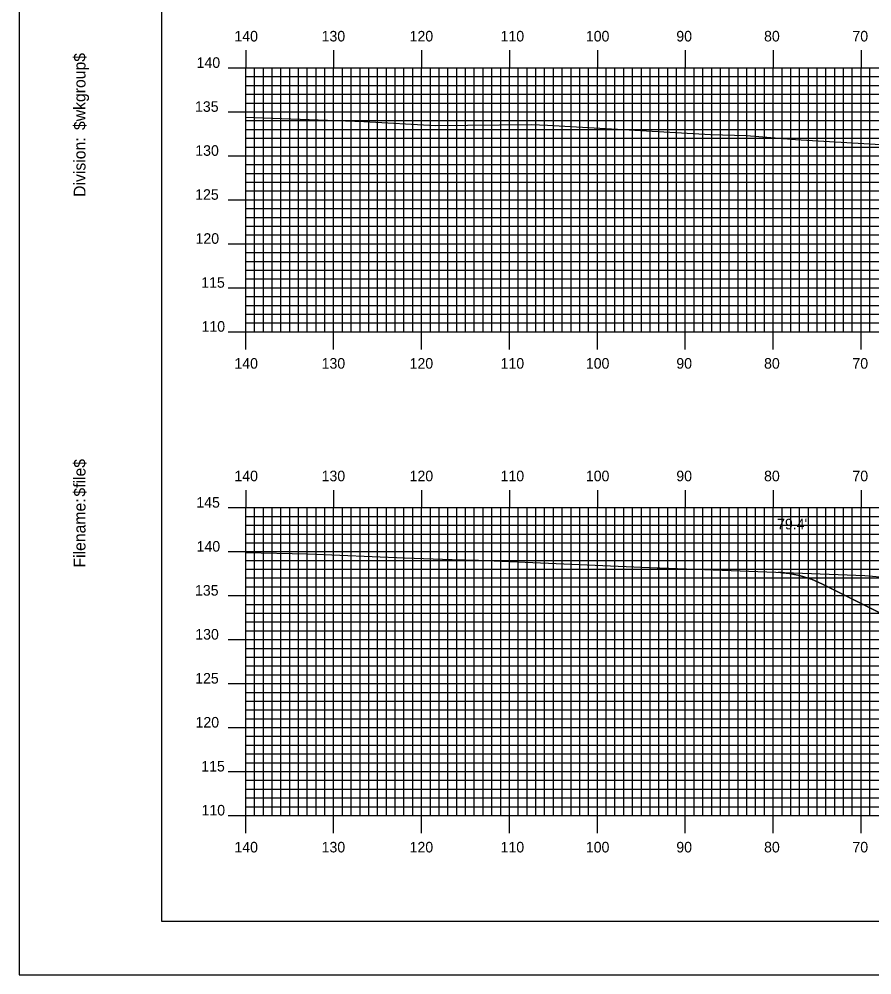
# Model space of a CAD drawing. Extents: x 1770842 to 1771185, y 442591 to 442811.
# Drawn here: x 1770841.8 to 1770938.8, y 442590.5 to 442699.2 of the extents above; entities that cross this region are included whole.
import ezdxf

# ---------------------------------------------------------------- set-up
doc = ezdxf.new("R2010")
doc.units = 0
for name, color, linetype in [('BORDER', 7, 'Continuous'), ('D_Roadway_Centerline', 7, 'Continuous'), ('D_Roadway_SlopeLines', 7, 'Continuous'), ('D_Text_Standard', 7, 'Continuous'), ('H_V ANNOTATION', 7, 'Continuous'), ('MAJOR', 7, 'Continuous'), ('MINOR', 7, 'Continuous'), ('PLOT BOUNDARY', 7, 'Continuous'), ('S_Roadway_Centerline', 7, 'Continuous')]:
    doc.layers.add(name, color=color, linetype=linetype)

msp = doc.modelspace()

# ---------------------------------------------------------------- linework, layer by layer
at = {"layer": 'BORDER'}
msp.add_lwpolyline([(1770857.95, 442596.67), (1771177.95, 442596.67), (1771177.95, 442806.67), (1770857.95, 442806.67)], close=True, dxfattribs=at)
at = {"layer": 'D_Roadway_Centerline'}
msp.add_lwpolyline([(1770928.14, 442636.32), (1770928.6, 442636.27), (1770929.39, 442636.2), (1770930.36, 442635.99), (1770930.64, 442635.93), (1770931.48, 442635.66), (1770931.89, 442635.53), (1770933.14, 442634.97), (1770933.14, 442634.97), (1770955.81, 442623.64), (1770973.37, 442614.86), (1770973.38, 442614.85), (1770977.38, 442615.85), (1770977.38, 442615.85), (1770987.55, 442618.4), (1770995.55, 442618.72), (1771007.55, 442618.96), (1771019.55, 442618.72), (1771027.55, 442618.4), (1771027.55, 442618.4), (1771037.73, 442615.85), (1771041.73, 442614.85), (1771041.74, 442614.86), (1771068.97, 442628.47)], dxfattribs=at)
at = {"layer": 'D_Roadway_SlopeLines'}
msp.add_lwpolyline([(1770973.38, 442614.85), (1770933.14, 442634.97), (1770931.89, 442635.53), (1770930.64, 442635.93), (1770929.39, 442636.2), (1770928.14, 442636.32)], dxfattribs=at)
at = {"layer": 'MAJOR'}
for p, q in [((1770867.55, 442695.67), (1770867.55, 442693.67)), ((1770877.55, 442695.67), (1770877.55, 442693.67)), ((1770887.55, 442695.67), (1770887.55, 442693.67)), ((1770897.55, 442695.67), (1770897.55, 442693.67)), ((1770907.55, 442695.67), (1770907.55, 442693.67)), ((1770917.55, 442695.67), (1770917.55, 442693.67)), ((1770927.55, 442695.67), (1770927.55, 442693.67)), ((1770937.55, 442695.67), (1770937.55, 442693.67)), ((1770865.55, 442693.67), (1770867.55, 442693.67)), ((1770867.55, 442693.67), (1771147.55, 442693.67)), ((1770867.55, 442663.67), (1770867.55, 442693.67)), ((1770867.55, 442663.67), (1770867.55, 442693.67)), ((1770867.55, 442693.67), (1771147.55, 442693.67)), ((1770877.55, 442663.67), (1770877.55, 442693.67)), ((1770887.55, 442663.67), (1770887.55, 442693.67)), ((1770897.55, 442663.67), (1770897.55, 442693.67)), ((1770907.55, 442663.67), (1770907.55, 442693.67)), ((1770917.55, 442663.67), (1770917.55, 442693.67)), ((1770927.55, 442663.67), (1770927.55, 442693.67)), ((1770937.55, 442663.67), (1770937.55, 442693.67)), ((1770865.55, 442688.67), (1770867.55, 442688.67)), ((1770867.55, 442688.67), (1771147.55, 442688.67)), ((1770865.55, 442683.67), (1770867.55, 442683.67)), ((1770867.55, 442683.67), (1771147.55, 442683.67)), ((1770865.55, 442678.67), (1770867.55, 442678.67)), ((1770867.55, 442678.67), (1771147.55, 442678.67)), ((1770865.55, 442673.67), (1770867.55, 442673.67)), ((1770867.55, 442673.67), (1771147.55, 442673.67)), ((1770865.55, 442668.67), (1770867.55, 442668.67)), ((1770867.55, 442668.67), (1771147.55, 442668.67)), ((1770865.55, 442663.67), (1770867.55, 442663.67)), ((1770867.55, 442663.67), (1771147.55, 442663.67)), ((1770867.55, 442663.67), (1771147.55, 442663.67)), ((1770867.55, 442661.66), (1770867.55, 442663.67)), ((1770877.55, 442661.66), (1770877.55, 442663.67)), ((1770887.55, 442661.66), (1770887.55, 442663.67)), ((1770897.55, 442661.66), (1770897.55, 442663.67)), ((1770907.55, 442661.66), (1770907.55, 442663.67)), ((1770917.55, 442661.66), (1770917.55, 442663.67)), ((1770927.55, 442661.66), (1770927.55, 442663.67)), ((1770937.55, 442661.66), (1770937.55, 442663.67)), ((1770867.55, 442645.67), (1770867.55, 442643.67)), ((1770877.55, 442645.67), (1770877.55, 442643.67)), ((1770887.55, 442645.67), (1770887.55, 442643.67)), ((1770897.55, 442645.67), (1770897.55, 442643.67)), ((1770907.55, 442645.67), (1770907.55, 442643.67)), ((1770917.55, 442645.67), (1770917.55, 442643.67)), ((1770927.55, 442645.67), (1770927.55, 442643.67)), ((1770937.55, 442645.67), (1770937.55, 442643.67)), ((1770865.55, 442643.67), (1770867.55, 442643.67)), ((1770867.55, 442643.67), (1771147.55, 442643.67)), ((1770867.55, 442608.67), (1770867.55, 442643.67)), ((1770867.55, 442608.67), (1770867.55, 442643.67)), ((1770867.55, 442643.67), (1771147.55, 442643.67)), ((1770877.55, 442608.67), (1770877.55, 442643.67)), ((1770887.55, 442608.67), (1770887.55, 442643.67)), ((1770897.55, 442608.67), (1770897.55, 442643.67)), ((1770907.55, 442608.67), (1770907.55, 442643.67)), ((1770917.55, 442608.67), (1770917.55, 442643.67)), ((1770927.55, 442608.67), (1770927.55, 442643.67)), ((1770937.55, 442608.67), (1770937.55, 442643.67)), ((1770865.55, 442638.67), (1770867.55, 442638.67)), ((1770867.55, 442638.67), (1771147.55, 442638.67)), ((1770865.55, 442633.67), (1770867.55, 442633.67)), ((1770867.55, 442633.67), (1771147.55, 442633.67)), ((1770865.55, 442628.67), (1770867.55, 442628.67)), ((1770867.55, 442628.67), (1771147.55, 442628.67)), ((1770865.55, 442623.67), (1770867.55, 442623.67)), ((1770867.55, 442623.67), (1771147.55, 442623.67)), ((1770865.55, 442618.67), (1770867.55, 442618.67)), ((1770867.55, 442618.67), (1771147.55, 442618.67)), ((1770865.55, 442613.67), (1770867.55, 442613.67)), ((1770867.55, 442613.67), (1771147.55, 442613.67)), ((1770865.55, 442608.67), (1770867.55, 442608.67)), ((1770867.55, 442608.67), (1771147.55, 442608.67)), ((1770867.55, 442608.67), (1771147.55, 442608.67)), ((1770867.55, 442606.66), (1770867.55, 442608.67)), ((1770877.55, 442606.66), (1770877.55, 442608.67)), ((1770887.55, 442606.66), (1770887.55, 442608.67)), ((1770897.55, 442606.66), (1770897.55, 442608.67)), ((1770907.55, 442606.66), (1770907.55, 442608.67)), ((1770917.55, 442606.66), (1770917.55, 442608.67)), ((1770927.55, 442606.66), (1770927.55, 442608.67)), ((1770937.55, 442606.66), (1770937.55, 442608.67))]:
    msp.add_line(p, q, dxfattribs=at)
at = {"layer": 'MINOR'}
for p, q in [((1770868.55, 442663.67), (1770868.55, 442693.67)), ((1770869.55, 442663.67), (1770869.55, 442693.67)), ((1770870.55, 442663.67), (1770870.55, 442693.67)), ((1770871.55, 442663.67), (1770871.55, 442693.67)), ((1770872.55, 442663.67), (1770872.55, 442693.67)), ((1770873.55, 442663.67), (1770873.55, 442693.67)), ((1770874.55, 442663.67), (1770874.55, 442693.67)), ((1770875.55, 442663.67), (1770875.55, 442693.67)), ((1770876.55, 442663.67), (1770876.55, 442693.67)), ((1770878.55, 442663.67), (1770878.55, 442693.67)), ((1770879.55, 442663.67), (1770879.55, 442693.67)), ((1770880.55, 442663.67), (1770880.55, 442693.67)), ((1770881.55, 442663.67), (1770881.55, 442693.67)), ((1770882.55, 442663.67), (1770882.55, 442693.67)), ((1770883.55, 442663.67), (1770883.55, 442693.67)), ((1770884.55, 442663.67), (1770884.55, 442693.67)), ((1770885.55, 442663.67), (1770885.55, 442693.67)), ((1770886.55, 442663.67), (1770886.55, 442693.67)), ((1770888.55, 442663.67), (1770888.55, 442693.67)), ((1770889.55, 442663.67), (1770889.55, 442693.67)), ((1770890.55, 442663.67), (1770890.55, 442693.67)), ((1770891.55, 442663.67), (1770891.55, 442693.67)), ((1770892.55, 442663.67), (1770892.55, 442693.67)), ((1770893.55, 442663.67), (1770893.55, 442693.67)), ((1770894.55, 442663.67), (1770894.55, 442693.67)), ((1770895.55, 442663.67), (1770895.55, 442693.67)), ((1770896.55, 442663.67), (1770896.55, 442693.67)), ((1770898.55, 442663.67), (1770898.55, 442693.67)), ((1770899.55, 442663.67), (1770899.55, 442693.67)), ((1770900.55, 442663.67), (1770900.55, 442693.67)), ((1770901.55, 442663.67), (1770901.55, 442693.67)), ((1770902.55, 442663.67), (1770902.55, 442693.67)), ((1770903.55, 442663.67), (1770903.55, 442693.67)), ((1770904.55, 442663.67), (1770904.55, 442693.67)), ((1770905.55, 442663.67), (1770905.55, 442693.67)), ((1770906.55, 442663.67), (1770906.55, 442693.67)), ((1770908.55, 442663.67), (1770908.55, 442693.67)), ((1770909.55, 442663.67), (1770909.55, 442693.67)), ((1770910.55, 442663.67), (1770910.55, 442693.67)), ((1770911.55, 442663.67), (1770911.55, 442693.67)), ((1770912.55, 442663.67), (1770912.55, 442693.67)), ((1770913.55, 442663.67), (1770913.55, 442693.67)), ((1770914.55, 442663.67), (1770914.55, 442693.67)), ((1770915.55, 442663.67), (1770915.55, 442693.67)), ((1770916.55, 442663.67), (1770916.55, 442693.67)), ((1770918.55, 442663.67), (1770918.55, 442693.67)), ((1770919.55, 442663.67), (1770919.55, 442693.67)), ((1770920.55, 442663.67), (1770920.55, 442693.67)), ((1770921.55, 442663.67), (1770921.55, 442693.67)), ((1770922.55, 442663.67), (1770922.55, 442693.67)), ((1770923.55, 442663.67), (1770923.55, 442693.67)), ((1770924.55, 442663.67), (1770924.55, 442693.67)), ((1770925.55, 442663.67), (1770925.55, 442693.67)), ((1770926.55, 442663.67), (1770926.55, 442693.67)), ((1770928.55, 442663.67), (1770928.55, 442693.67)), ((1770929.55, 442663.67), (1770929.55, 442693.67)), ((1770930.55, 442663.67), (1770930.55, 442693.67)), ((1770931.55, 442663.67), (1770931.55, 442693.67)), ((1770932.55, 442663.67), (1770932.55, 442693.67)), ((1770933.55, 442663.67), (1770933.55, 442693.67)), ((1770934.55, 442663.67), (1770934.55, 442693.67)), ((1770935.55, 442663.67), (1770935.55, 442693.67)), ((1770936.55, 442663.67), (1770936.55, 442693.67)), ((1770938.55, 442663.67), (1770938.55, 442693.67)), ((1770867.55, 442692.67), (1771147.55, 442692.67)), ((1770867.55, 442692.67), (1770869.56, 442692.67)), ((1770867.55, 442691.67), (1771147.55, 442691.67)), ((1770867.55, 442691.67), (1770869.56, 442691.67)), ((1770867.55, 442690.67), (1771147.55, 442690.67)), ((1770867.55, 442690.67), (1770869.56, 442690.67)), ((1770867.55, 442689.67), (1771147.55, 442689.67)), ((1770867.55, 442689.67), (1770869.56, 442689.67)), ((1770867.55, 442687.67), (1771147.55, 442687.67)), ((1770867.55, 442687.67), (1770869.56, 442687.67)), ((1770867.55, 442686.67), (1771147.55, 442686.67)), ((1770867.55, 442686.67), (1770869.56, 442686.67)), ((1770867.55, 442685.67), (1771147.55, 442685.67)), ((1770867.55, 442685.67), (1770869.56, 442685.67)), ((1770867.55, 442684.67), (1771147.55, 442684.67)), ((1770867.55, 442684.67), (1770869.56, 442684.67)), ((1770867.55, 442682.67), (1771147.55, 442682.67)), ((1770867.55, 442682.67), (1770869.56, 442682.67)), ((1770867.55, 442681.67), (1771147.55, 442681.67)), ((1770867.55, 442681.67), (1770869.56, 442681.67)), ((1770867.55, 442680.67), (1771147.55, 442680.67)), ((1770867.55, 442680.67), (1770869.56, 442680.67)), ((1770867.55, 442679.67), (1771147.55, 442679.67)), ((1770867.55, 442679.67), (1770869.56, 442679.67)), ((1770867.55, 442677.67), (1771147.55, 442677.67)), ((1770867.55, 442677.67), (1770869.56, 442677.67)), ((1770867.55, 442676.67), (1771147.55, 442676.67)), ((1770867.55, 442676.67), (1770869.56, 442676.67)), ((1770867.55, 442675.67), (1771147.55, 442675.67)), ((1770867.55, 442675.67), (1770869.56, 442675.67)), ((1770867.55, 442674.67), (1771147.55, 442674.67)), ((1770867.55, 442674.67), (1770869.56, 442674.67)), ((1770867.55, 442672.67), (1771147.55, 442672.67)), ((1770867.55, 442672.67), (1770869.56, 442672.67)), ((1770867.55, 442671.67), (1771147.55, 442671.67)), ((1770867.55, 442671.67), (1770869.56, 442671.67)), ((1770867.55, 442670.67), (1771147.55, 442670.67)), ((1770867.55, 442670.67), (1770869.56, 442670.67)), ((1770867.55, 442669.67), (1771147.55, 442669.67)), ((1770867.55, 442669.67), (1770869.56, 442669.67)), ((1770867.55, 442667.67), (1771147.55, 442667.67)), ((1770867.55, 442667.67), (1770869.56, 442667.67)), ((1770867.55, 442666.67), (1771147.55, 442666.67)), ((1770867.55, 442666.67), (1770869.56, 442666.67)), ((1770867.55, 442665.67), (1771147.55, 442665.67)), ((1770867.55, 442665.67), (1770869.56, 442665.67)), ((1770867.55, 442664.67), (1771147.55, 442664.67)), ((1770867.55, 442664.67), (1770869.56, 442664.67)), ((1770868.55, 442608.67), (1770868.55, 442643.67)), ((1770869.55, 442608.67), (1770869.55, 442643.67)), ((1770870.55, 442608.67), (1770870.55, 442643.67)), ((1770871.55, 442608.67), (1770871.55, 442643.67)), ((1770872.55, 442608.67), (1770872.55, 442643.67)), ((1770873.55, 442608.67), (1770873.55, 442643.67)), ((1770874.55, 442608.67), (1770874.55, 442643.67)), ((1770875.55, 442608.67), (1770875.55, 442643.67)), ((1770876.55, 442608.67), (1770876.55, 442643.67)), ((1770878.55, 442608.67), (1770878.55, 442643.67)), ((1770879.55, 442608.67), (1770879.55, 442643.67)), ((1770880.55, 442608.67), (1770880.55, 442643.67)), ((1770881.55, 442608.67), (1770881.55, 442643.67)), ((1770882.55, 442608.67), (1770882.55, 442643.67)), ((1770883.55, 442608.67), (1770883.55, 442643.67)), ((1770884.55, 442608.67), (1770884.55, 442643.67)), ((1770885.55, 442608.67), (1770885.55, 442643.67)), ((1770886.55, 442608.67), (1770886.55, 442643.67)), ((1770888.55, 442608.67), (1770888.55, 442643.67)), ((1770889.55, 442608.67), (1770889.55, 442643.67)), ((1770890.55, 442608.67), (1770890.55, 442643.67)), ((1770891.55, 442608.67), (1770891.55, 442643.67)), ((1770892.55, 442608.67), (1770892.55, 442643.67)), ((1770893.55, 442608.67), (1770893.55, 442643.67)), ((1770894.55, 442608.67), (1770894.55, 442643.67)), ((1770895.55, 442608.67), (1770895.55, 442643.67)), ((1770896.55, 442608.67), (1770896.55, 442643.67)), ((1770898.55, 442608.67), (1770898.55, 442643.67)), ((1770899.55, 442608.67), (1770899.55, 442643.67)), ((1770900.55, 442608.67), (1770900.55, 442643.67)), ((1770901.55, 442608.67), (1770901.55, 442643.67)), ((1770902.55, 442608.67), (1770902.55, 442643.67)), ((1770903.55, 442608.67), (1770903.55, 442643.67)), ((1770904.55, 442608.67), (1770904.55, 442643.67)), ((1770905.55, 442608.67), (1770905.55, 442643.67)), ((1770906.55, 442608.67), (1770906.55, 442643.67)), ((1770908.55, 442608.67), (1770908.55, 442643.67)), ((1770909.55, 442608.67), (1770909.55, 442643.67)), ((1770910.55, 442608.67), (1770910.55, 442643.67)), ((1770911.55, 442608.67), (1770911.55, 442643.67)), ((1770912.55, 442608.67), (1770912.55, 442643.67)), ((1770913.55, 442608.67), (1770913.55, 442643.67)), ((1770914.55, 442608.67), (1770914.55, 442643.67)), ((1770915.55, 442608.67), (1770915.55, 442643.67)), ((1770916.55, 442608.67), (1770916.55, 442643.67)), ((1770918.55, 442608.67), (1770918.55, 442643.67)), ((1770919.55, 442608.67), (1770919.55, 442643.67)), ((1770920.55, 442608.67), (1770920.55, 442643.67)), ((1770921.55, 442608.67), (1770921.55, 442643.67)), ((1770922.55, 442608.67), (1770922.55, 442643.67)), ((1770923.55, 442608.67), (1770923.55, 442643.67)), ((1770924.55, 442608.67), (1770924.55, 442643.67)), ((1770925.55, 442608.67), (1770925.55, 442643.67)), ((1770926.55, 442608.67), (1770926.55, 442643.67)), ((1770928.55, 442608.67), (1770928.55, 442643.67)), ((1770929.55, 442608.67), (1770929.55, 442643.67)), ((1770930.55, 442608.67), (1770930.55, 442643.67)), ((1770931.55, 442608.67), (1770931.55, 442643.67)), ((1770932.55, 442608.67), (1770932.55, 442643.67)), ((1770933.55, 442608.67), (1770933.55, 442643.67)), ((1770934.55, 442608.67), (1770934.55, 442643.67)), ((1770935.55, 442608.67), (1770935.55, 442643.67)), ((1770936.55, 442608.67), (1770936.55, 442643.67)), ((1770938.55, 442608.67), (1770938.55, 442643.67)), ((1770867.55, 442642.67), (1771147.55, 442642.67)), ((1770867.55, 442642.67), (1770869.56, 442642.67)), ((1770867.55, 442641.67), (1771147.55, 442641.67)), ((1770867.55, 442641.67), (1770869.56, 442641.67)), ((1770867.55, 442640.67), (1771147.55, 442640.67)), ((1770867.55, 442640.67), (1770869.56, 442640.67)), ((1770867.55, 442639.67), (1771147.55, 442639.67)), ((1770867.55, 442639.67), (1770869.56, 442639.67)), ((1770867.55, 442637.67), (1771147.55, 442637.67)), ((1770867.55, 442637.67), (1770869.56, 442637.67)), ((1770867.55, 442636.67), (1771147.55, 442636.67)), ((1770867.55, 442636.67), (1770869.56, 442636.67)), ((1770867.55, 442635.67), (1771147.55, 442635.67)), ((1770867.55, 442635.67), (1770869.56, 442635.67)), ((1770867.55, 442634.67), (1771147.55, 442634.67)), ((1770867.55, 442634.67), (1770869.56, 442634.67)), ((1770867.55, 442632.67), (1771147.55, 442632.67)), ((1770867.55, 442632.67), (1770869.56, 442632.67)), ((1770867.55, 442631.67), (1771147.55, 442631.67)), ((1770867.55, 442631.67), (1770869.56, 442631.67)), ((1770867.55, 442630.67), (1771147.55, 442630.67)), ((1770867.55, 442630.67), (1770869.56, 442630.67)), ((1770867.55, 442629.67), (1771147.55, 442629.67)), ((1770867.55, 442629.67), (1770869.56, 442629.67)), ((1770867.55, 442627.67), (1771147.55, 442627.67)), ((1770867.55, 442627.67), (1770869.56, 442627.67)), ((1770867.55, 442626.67), (1771147.55, 442626.67)), ((1770867.55, 442626.67), (1770869.56, 442626.67)), ((1770867.55, 442625.67), (1771147.55, 442625.67)), ((1770867.55, 442625.67), (1770869.56, 442625.67)), ((1770867.55, 442624.67), (1771147.55, 442624.67)), ((1770867.55, 442624.67), (1770869.56, 442624.67)), ((1770867.55, 442622.67), (1771147.55, 442622.67)), ((1770867.55, 442622.67), (1770869.56, 442622.67)), ((1770867.55, 442621.67), (1771147.55, 442621.67)), ((1770867.55, 442621.67), (1770869.56, 442621.67)), ((1770867.55, 442620.67), (1771147.55, 442620.67)), ((1770867.55, 442620.67), (1770869.56, 442620.67)), ((1770867.55, 442619.67), (1771147.55, 442619.67)), ((1770867.55, 442619.67), (1770869.56, 442619.67)), ((1770867.55, 442617.67), (1771147.55, 442617.67)), ((1770867.55, 442617.67), (1770869.56, 442617.67)), ((1770867.55, 442616.67), (1771147.55, 442616.67)), ((1770867.55, 442616.67), (1770869.56, 442616.67)), ((1770867.55, 442615.67), (1771147.55, 442615.67)), ((1770867.55, 442615.67), (1770869.56, 442615.67)), ((1770867.55, 442614.67), (1771147.55, 442614.67)), ((1770867.55, 442614.67), (1770869.56, 442614.67)), ((1770867.55, 442612.67), (1771147.55, 442612.67)), ((1770867.55, 442612.67), (1770869.56, 442612.67)), ((1770867.55, 442611.67), (1771147.55, 442611.67)), ((1770867.55, 442611.67), (1770869.56, 442611.67)), ((1770867.55, 442610.67), (1771147.55, 442610.67)), ((1770867.55, 442610.67), (1770869.56, 442610.67)), ((1770867.55, 442609.67), (1771147.55, 442609.67)), ((1770867.55, 442609.67), (1770869.56, 442609.67))]:
    msp.add_line(p, q, dxfattribs=at)
at = {"layer": 'PLOT BOUNDARY'}
msp.add_lwpolyline([(1770841.77, 442590.55), (1771181.77, 442590.55), (1771181.77, 442810.55), (1770841.77, 442810.55)], close=True, dxfattribs=at)
at = {"layer": 'S_Roadway_Centerline'}
for points in [[(1770867.55, 442688.08), (1770871.67, 442687.93), (1770880.98, 442687.58), (1770889.14, 442687.11), (1770900.06, 442687.24), (1770901.88, 442687.15), (1770920.41, 442686.09), (1770924.52, 442685.96), (1770930.09, 442685.53), (1770939.79, 442684.95)], [(1770867.55, 442638.58), (1770874.59, 442638.4), (1770885.6, 442637.98), (1770891.02, 442637.77), (1770894.04, 442637.69), (1770914.35, 442636.84), (1770914.56, 442636.83), (1770914.59, 442636.83), (1770914.64, 442636.83), (1770937.99, 442635.94), (1770944.06, 442635.42)]]:
    msp.add_lwpolyline(points, dxfattribs=at)

# ---------------------------------------------------------------- texts
at = {"layer": 'BORDER'}
for s, p in [('$wkgroup$', (1770849.32, 442686.6)), ('Division:', (1770849.32, 442679)), ('$file$', (1770849.32, 442644.92)), ('Filename:', (1770849.32, 442636.86))]:
    msp.add_text(s, height=1.339, rotation=90, dxfattribs=at).set_placement(p)
at = {"layer": 'D_Text_Standard'}
msp.add_text("79.4'", height=1.2, dxfattribs=at).set_placement((1770927.99, 442641.2))
at = {"layer": 'H_V ANNOTATION'}
for s, p in [('140', (1770866.26, 442696.67)), ('130', (1770876.18, 442696.67)), ('120', (1770886.19, 442696.67)), ('110', (1770896.54, 442696.67)), ('100', (1770906.24, 442696.67)), ('90', (1770916.53, 442696.67)), ('80', (1770926.51, 442696.67)), ('70', (1770936.56, 442696.67)), ('140', (1770861.96, 442693.67)), ('135', (1770861.78, 442688.67)), ('130', (1770861.81, 442683.67)), ('125', (1770861.8, 442678.67)), ('120', (1770861.84, 442673.67)), ('115', (1770862.49, 442668.67)), ('110', (1770862.52, 442663.67)), ('140', (1770866.26, 442659.47)), ('130', (1770876.18, 442659.47)), ('120', (1770886.19, 442659.47)), ('110', (1770896.54, 442659.47)), ('100', (1770906.24, 442659.47)), ('90', (1770916.53, 442659.47)), ('80', (1770926.51, 442659.47)), ('70', (1770936.56, 442659.47)), ('140', (1770866.26, 442646.67)), ('130', (1770876.18, 442646.67)), ('120', (1770886.19, 442646.67)), ('110', (1770896.54, 442646.67)), ('100', (1770906.24, 442646.67)), ('90', (1770916.53, 442646.67)), ('80', (1770926.51, 442646.67)), ('70', (1770936.56, 442646.67)), ('145', (1770861.93, 442643.67)), ('140', (1770861.96, 442638.67)), ('135', (1770861.78, 442633.67)), ('130', (1770861.81, 442628.67)), ('125', (1770861.8, 442623.67)), ('120', (1770861.84, 442618.67)), ('115', (1770862.49, 442613.67)), ('110', (1770862.52, 442608.67)), ('140', (1770866.26, 442604.47)), ('130', (1770876.18, 442604.47)), ('120', (1770886.19, 442604.47)), ('110', (1770896.54, 442604.47)), ('100', (1770906.24, 442604.47)), ('90', (1770916.53, 442604.47)), ('80', (1770926.51, 442604.47)), ('70', (1770936.56, 442604.47))]:
    msp.add_text(s, height=1.2, dxfattribs=at).set_placement(p)
at = {"layer": 'MAJOR'}
for p in [(1770867.55, 442663.67), (1770867.55, 442608.67)]:
    msp.add_text('-', height=0.012, dxfattribs=at).set_placement(p)

doc.saveas('drawing.dxf')
